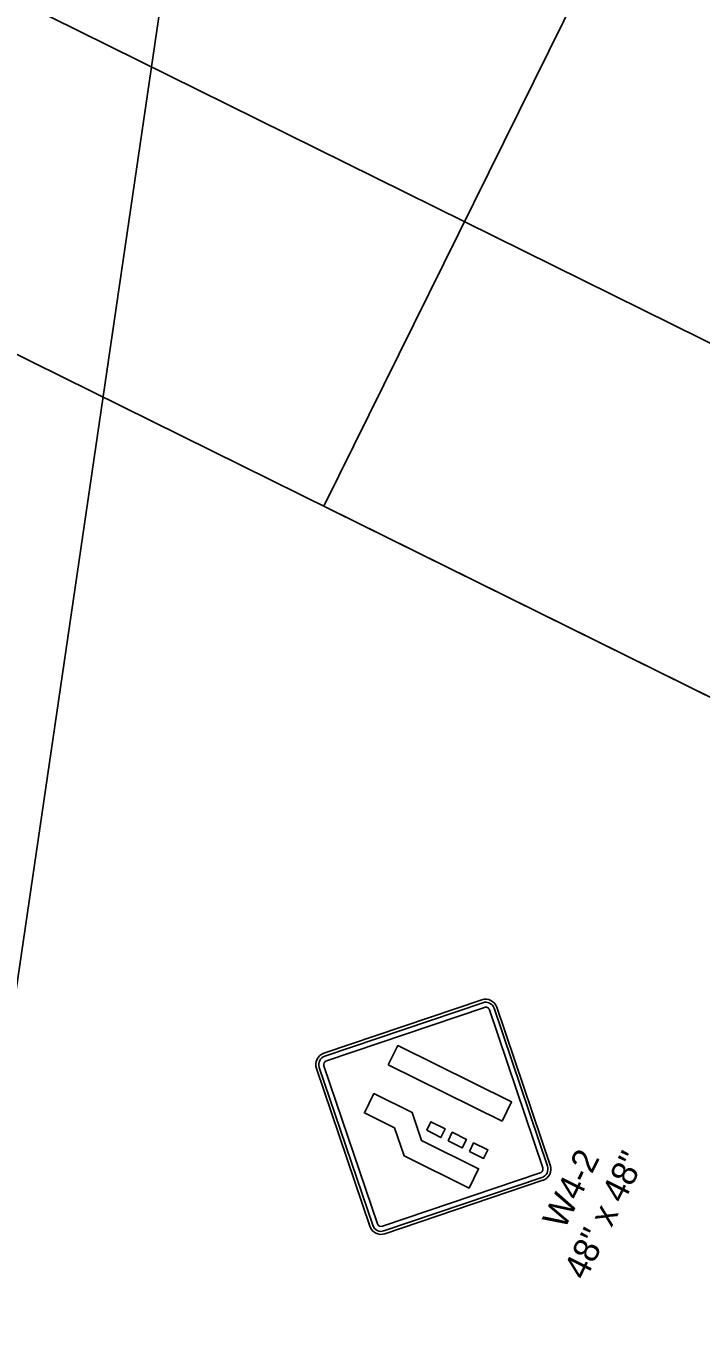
# Model space of a CAD drawing. Extents: x 14104283 to 14128447, y 8633203 to 8671666.
# Drawn here: x 14119412.3 to 14119624.9, y 8669892.2 to 8670301 of the extents above; entities that cross this region are included whole.
import ezdxf

# ---------------------------------------------------------------- set-up
doc = ezdxf.new("R2010")
doc.units = 0
for name, color, linetype in [('Cell', 7, 'Continuous'), ('dsnNonPlotable', 7, 'Continuous'), ('dsnStdLabel', 7, 'Continuous')]:
    doc.layers.add(name, color=color, linetype=linetype)

msp = doc.modelspace()

# ---------------------------------------------------------------- linework, layer by layer
at = {"layer": 'Cell'}
for p, q in [((14119506.16, 8669977.48), (14119555.9, 8669994.31)), ((14119555.9, 8669994.31), (14119506.16, 8669977.48)), ((14119506.47, 8669976.6), (14119556.2, 8669993.42)), ((14119556.7, 8669991.94), (14119506.97, 8669975.12)), ((14119575.11, 8669941.43), (14119558.28, 8669991.16)), ((14119559.76, 8669991.66), (14119576.59, 8669941.93)), ((14119560.65, 8669991.96), (14119577.47, 8669942.23)), ((14119577.47, 8669942.23), (14119560.65, 8669991.96)), ((14119520.64, 8669923), (14119503.81, 8669972.73)), ((14119503.81, 8669972.73), (14119520.64, 8669923)), ((14119503.81, 8669972.73), (14119503.81, 8669972.73)), ((14119521.53, 8669923.3), (14119504.7, 8669973.03)), ((14119506.18, 8669973.53), (14119506.18, 8669973.53)), ((14119506.18, 8669973.53), (14119523.01, 8669923.8)), ((14119524.59, 8669923.02), (14119574.32, 8669939.84)), ((14119574.82, 8669938.36), (14119525.09, 8669921.54)), ((14119575.12, 8669937.47), (14119525.39, 8669920.65)), ((14119525.39, 8669920.65), (14119575.12, 8669937.47))]:
    msp.add_line(p, q, dxfattribs=at)
for points in [[(14119556.2, 8669993.42), (14119506.47, 8669976.6)], [(14119556.7, 8669991.94), (14119506.96, 8669975.12)], [(14119575.11, 8669941.43), (14119558.28, 8669991.16)], [(14119576.59, 8669941.93), (14119559.76, 8669991.66)], [(14119504.7, 8669973.03), (14119521.53, 8669923.3)], [(14119506.18, 8669973.53), (14119523.01, 8669923.8)], [(14119524.59, 8669923.02), (14119574.32, 8669939.84)], [(14119525.09, 8669921.54), (14119574.82, 8669938.36)]]:
    msp.add_lwpolyline(points, dxfattribs=at)
for points in [[(14119526.43, 8669973.85), (14119562.29, 8669956.12), (14119565.28, 8669962.17), (14119529.42, 8669979.9)], [(14119528.43, 8669954.03), (14119531.43, 8669945.16), (14119551.87, 8669935.05), (14119554.86, 8669941.11), (14119536.93, 8669949.97), (14119533.93, 8669958.85), (14119521.94, 8669964.77), (14119518.95, 8669958.72)], [(14119538.54, 8669953.22), (14119539.87, 8669955.91), (14119544.35, 8669953.69), (14119543.02, 8669951)], [(14119545.26, 8669949.9), (14119546.59, 8669952.59), (14119551.07, 8669950.37), (14119549.74, 8669947.68)], [(14119551.99, 8669946.57), (14119553.32, 8669949.26), (14119557.8, 8669947.05), (14119556.47, 8669944.36)]]:
    msp.add_lwpolyline(points, close=True, dxfattribs=at)
for centre, radius, start, end in [((14119557.1, 8669990.76), 3.75, 18.6912, 108.6914), ((14119557.1, 8669990.76), 3.75, 18.6912, 108.6914), ((14119557.1, 8669990.76), 2.81, 18.6912, 108.6914), ((14119557.1, 8669990.76), 2.81, 18.6912, 108.6914), ((14119557.1, 8669990.76), 1.25, 18.6912, 108.6914), ((14119557.1, 8669990.76), 1.25, 18.6912, 108.6914), ((14119507.37, 8669973.93), 3.75, 108.6914, 198.6912), ((14119507.37, 8669973.93), 3.75, 108.6914, 198.6912), ((14119507.37, 8669973.93), 2.81, 108.6914, 198.6912), ((14119507.37, 8669973.93), 2.81, 108.6914, 198.6912), ((14119507.37, 8669973.93), 1.25, 108.6914, 198.6912), ((14119507.37, 8669973.93), 1.25, 108.6914, 198.6912), ((14119573.92, 8669941.02), 1.25, 288.691, 18.6912), ((14119573.92, 8669941.02), 1.25, 288.691, 18.6912), ((14119573.92, 8669941.02), 2.81, 288.691, 18.6912), ((14119573.92, 8669941.02), 2.81, 288.691, 18.6912), ((14119573.92, 8669941.02), 3.75, 288.691, 18.6912), ((14119573.92, 8669941.02), 3.75, 288.691, 18.6912), ((14119524.19, 8669924.2), 3.75, 198.6914, 288.691), ((14119524.19, 8669924.2), 3.75, 198.6914, 288.691), ((14119524.19, 8669924.2), 2.81, 198.6914, 288.691), ((14119524.19, 8669924.2), 2.81, 198.6914, 288.691), ((14119524.19, 8669924.2), 1.25, 198.6914, 288.691), ((14119524.19, 8669924.2), 1.25, 198.6914, 288.691)]:
    msp.add_arc(centre, radius, start, end, dxfattribs=at)
at = {"layer": 'dsnNonPlotable'}
for points in [[(14119282.05, 8670260.59), (14119976.78, 8671665.73), (14120882.16, 8671218.09), (14120187.43, 8669812.95)], [(14119506.15, 8670149.79), (14120200.88, 8671554.92), (14120653.57, 8671331.1), (14119958.84, 8669925.97)], [(14118774.15, 8669147.84), (14119001.66, 8670698.74), (14119501.31, 8670625.45), (14119273.81, 8669074.54)], [(14118631.64, 8668945.1), (14119326.37, 8670350.23), (14120231.75, 8669902.59), (14119537.02, 8668497.46)]]:
    msp.add_lwpolyline(points, close=True, dxfattribs=at)
at = {"layer": 'dsnStdLabel'}
msp.add_arc((14116600.71, 8671268.95), 3350.16, 328.57258, 335.97179, dxfattribs=at)

# ---------------------------------------------------------------- texts
at = {"layer": 'Cell'}
for s, p in [('W4-2', (14119581.87, 8669921.65)), ('48" x 48"', (14119588.48, 8669905.69))]:
    msp.add_text(s, height=8, rotation=63.6912, dxfattribs=at).set_placement(p)

doc.saveas('drawing.dxf')
